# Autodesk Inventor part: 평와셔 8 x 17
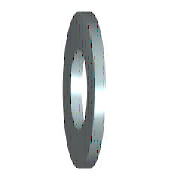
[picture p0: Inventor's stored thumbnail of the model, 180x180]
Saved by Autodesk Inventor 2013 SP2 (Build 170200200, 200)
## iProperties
IsCustomPart: 1
Created: 2012-02
Part Number: 평와셔 8 x 17
Material: 강철, 연강
Description: 평면 와셔
Document SubType Name: Modeling
Standard: KS B 1326
Designer: mduedu
Standards Organization: KS
Language: ko-KR
Size Designation: 8x17
Categories: <MemberInstance><Categories><Category DisplayName="조임쇠" InternalName="e4da775c-781d-43d5-af7c-5136215cf5a6" Mnemonic="FSTN"><Category DisplayName="와셔" InternalN
Density: 1 g/cm^3
Author: mduedu
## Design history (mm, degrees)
sketch "스케치"
  geometry: C1 r 8.5 at (0, 0); C2 r 4.2 at (0, 0); 1 further point
  constraints: 2 centre point, 2 coincident
  dimensions: "d0" = 8.4 diameter of C2 (= SD1); "d1" = 17 diameter of C1 (= SD2)
extrude "본체" new body sketch "스케치" distance "d2" = 1.6 (= SD); taper "d3" = 0 deg
workaxis "Work Axis1"
workplane "Work Plane1"
body "Solid1"
other parameters: "SD1" = 8.4 [user parameter; used in 1 equation term], "SD2" = 17 [user parameter; used in 1 equation term], "SD" = 1.6 [user parameter; used in 1 equation term], "d4" = 0, "d5" = 0, "d6" = 0, "d7" = 0, "NND" = 8 [user parameter]
